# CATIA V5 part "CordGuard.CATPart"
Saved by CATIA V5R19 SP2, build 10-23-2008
Part number: CordGuard
Revision: ANY
Definition: UNKNOWN
Nomenclature: CordGuard
Source: Unknown
Bounding box of the stored display mesh (mm): x 0 to 80, y -10 to 10, z -10 to 10
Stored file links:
  Z:\fausse table rondelle-20220905T211342Z-001\fausse table rondelle\CordGuard.CATPart
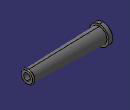
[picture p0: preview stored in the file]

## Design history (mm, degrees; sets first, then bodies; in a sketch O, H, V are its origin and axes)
AxisSystem1: origin (0, 0, 0), X (1, 0, 0), Y (0, 1, 0), Z (0, 0, 1)
Body1 "Verrundung1" (main body)
  Solid1: solid without history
